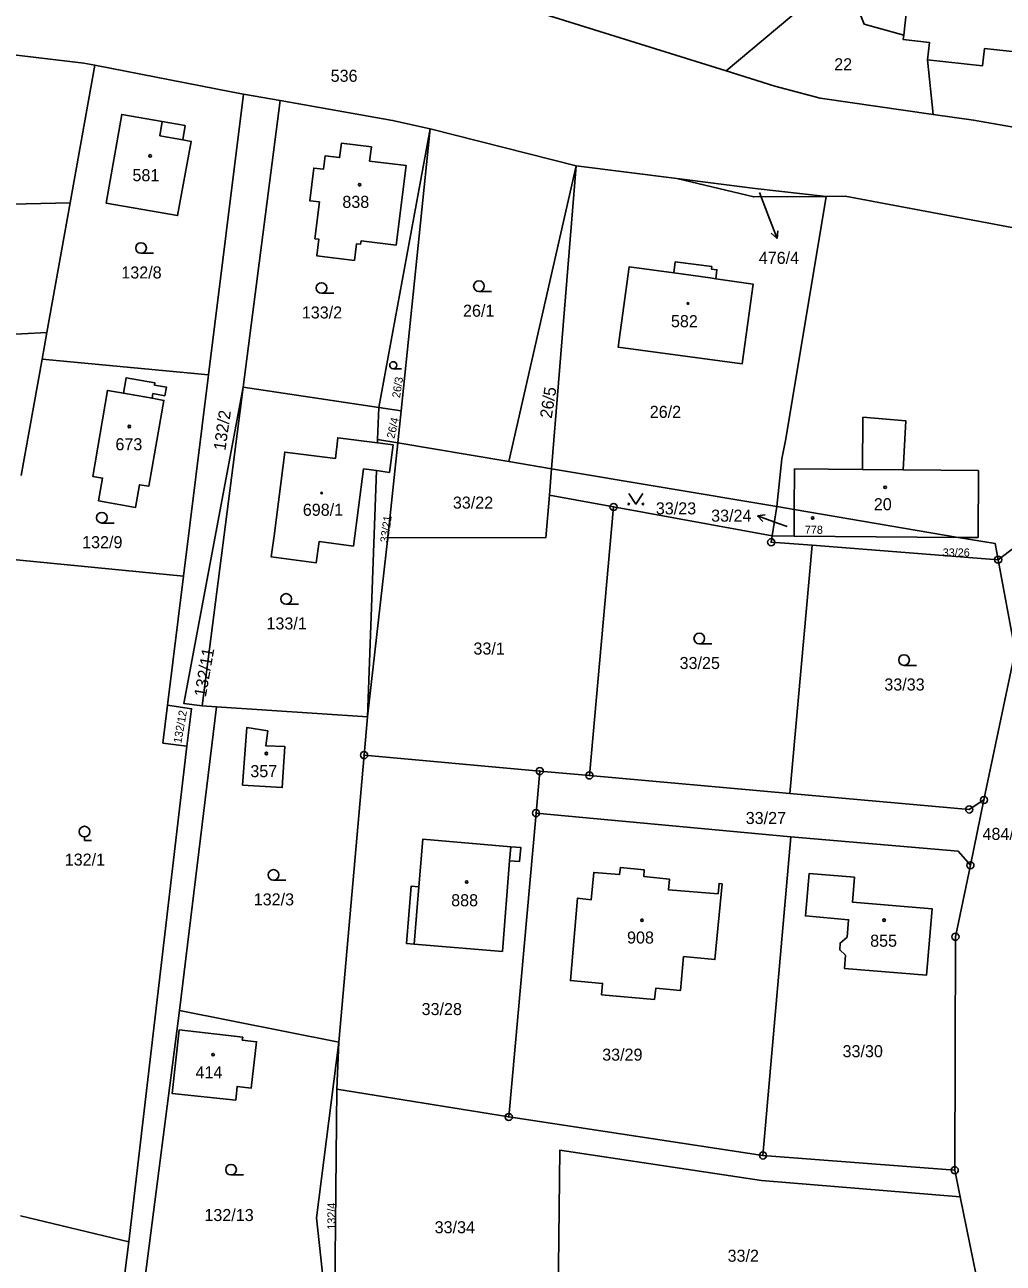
# Model space of a CAD drawing. Extents: x -725728 to -720881, y -1068679 to -1063504.
# Drawn here: x -724769.7 to -724631.7, y -1067201.5 to -1067026.9 of the extents above; entities that cross this region are included whole.
import ezdxf

# ---------------------------------------------------------------- set-up
doc = ezdxf.new("R2010")
doc.units = 0
for name, color, linetype in [('Hranice parcel', 7, 'Continuous'), ('Parcelní čísla', 7, 'Continuous'), ('Pop  PČ popisy', 7, 'Continuous'), ('Vnitřní kresba', 7, 'Continuous'), ('Značky bodu BP', 7, 'Continuous'), ('Značky budov', 7, 'Continuous'), ('Značky kultur', 7, 'Continuous')]:
    doc.layers.add(name, color=color, linetype=linetype)

# ---------------------------------------------------------------- blocks, each defined once
blk = doc.blocks.new('4.02_5')
at = {"layer": 'Značky budov'}
blk.add_circle((0, 0), 0.0117, dxfattribs=at)
blk = doc.blocks.new('4.02_4')
at = {"layer": 'Značky budov'}
blk.add_circle((-0.001, 0), 0.0175, dxfattribs=at)
blk = doc.blocks.new('4.02_3')
at = {"layer": 'Značky budov'}
blk.add_circle((-0.001, 0), 0.0175, dxfattribs=at)
blk = doc.blocks.new('1029_92')
at = {"layer": 'Pop  PČ popisy'}
for p, q in [((0, 0), (0.107, -0.28)), ((0.107, -0.28), (0.118, -0.169)), ((0.107, -0.28), (0.025, -0.205))]:
    blk.add_line(p, q, dxfattribs=at)
blk = doc.blocks.new('1029_94')
at = {"layer": 'Pop  PČ popisy'}
for p, q in [((-0.282, 0.102), (-0.171, 0.115)), ((0, 0), (-0.282, 0.102)), ((-0.282, 0.102), (-0.205, 0.021))]:
    blk.add_line(p, q, dxfattribs=at)
blk = doc.blocks.new('3.04_2')
at = {"layer": 'Značky kultur'}
blk.add_line((0.001, 0), (0.176, 0), dxfattribs=at)
blk.add_circle((0.001, 0.075), 0.075, dxfattribs=at)
blk = doc.blocks.new('3.04_5')
at = {"layer": 'Značky kultur'}
blk.add_line((0, 0), (0.118, 0), dxfattribs=at)
blk.add_circle((0, 0.05), 0.0502, dxfattribs=at)
blk = doc.blocks.new('3.14_1')
at = {"layer": 'Značky kultur'}
blk.add_lwpolyline([(-0.1, 0.15), (0, 0), (0.1, 0.15)], dxfattribs=at)
for centre in [(-0.1, 0), (0.1, 0)]:
    blk.add_circle(centre, 0.01, dxfattribs=at)
blk = doc.blocks.new('3.05_2')
at = {"layer": 'Značky kultur'}
for p, q in [((0, 0.05), (0, 0)), ((0, 0), (0.1, 0))]:
    blk.add_line(p, q, dxfattribs=at)
blk.add_circle((0, 0.125), 0.075, dxfattribs=at)
blk = doc.blocks.new('3.04_3')
at = {"layer": 'Značky kultur'}
blk.add_line((0.001, 0), (0.176, 0), dxfattribs=at)
blk.add_circle((0.001, 0.075), 0.075, dxfattribs=at)
blk = doc.blocks.new('1.05_2')
at = {"layer": 'Značky bodu BP'}
for radius in [0.05, 0.00303]:
    blk.add_circle((0, 0), radius, dxfattribs=at)
blk = doc.blocks.new('1.05_1')
at = {"layer": 'Značky bodu BP'}
for radius in [0.05, 0.00303]:
    blk.add_circle((0, 0), radius, dxfattribs=at)

msp = doc.modelspace()

# ---------------------------------------------------------------- linework, layer by layer
at = {"layer": 'Hranice parcel'}
for p, q in [((-724654.25, -1067019.5), (-724670.79, -1067033.37)), ((-724759.85, -1067032.59), (-724763.32, -1067051.97)), ((-724641.56, -1067039.51), (-724642.37, -1067031.81)), ((-724738.88, -1067036.65), (-724743.79, -1067076.25)), ((-724738.92, -1067077.99), (-724733.71, -1067037.56)), ((-724733.71, -1067037.56), (-724738.88, -1067036.65)), ((-724712.52, -1067041.56), (-724719.79, -1067080.85)), ((-724712.52, -1067041.56), (-724716.63, -1067081.32)), ((-724691.94, -1067046.77), (-724712.52, -1067041.56)), ((-724701.43, -1067088.49), (-724691.94, -1067046.77)), ((-724691.94, -1067046.77), (-724695.41, -1067089.5)), ((-724677.75, -1067048.56), (-724691.94, -1067046.77)), ((-724795.59, -1067052.75), (-724763.32, -1067051.97)), ((-724763.32, -1067051.97), (-724766.6, -1067070.28)), ((-724786.39, -1067071.29), (-724766.6, -1067070.28)), ((-724766.6, -1067070.28), (-724767.27, -1067074.02)), ((-724767.27, -1067074.02), (-724770.22, -1067090.46)), ((-724767.27, -1067074.02), (-724743.79, -1067076.25)), ((-724743.79, -1067076.25), (-724747.31, -1067104.65)), ((-724738.92, -1067077.99), (-724744.71, -1067122.95)), ((-724719.79, -1067080.85), (-724738.92, -1067077.99)), ((-724719.79, -1067080.85), (-724719.95, -1067085.37)), ((-724719.79, -1067080.85), (-724716.63, -1067081.32)), ((-724716.63, -1067081.32), (-724717.11, -1067085.85)), ((-724719.95, -1067085.37), (-724719.97, -1067085.85)), ((-724719.95, -1067085.37), (-724717.11, -1067085.85)), ((-724718.52, -1067099.21), (-724717.11, -1067085.85)), ((-724717.11, -1067085.85), (-724701.43, -1067088.49)), ((-724701.43, -1067088.49), (-724695.41, -1067089.5)), ((-724720.11, -1067089.76), (-724721.37, -1067124.47)), ((-724695.71, -1067093.21), (-724695.41, -1067089.5)), ((-724695.41, -1067089.5), (-724663.61, -1067094.84)), ((-724686.67, -1067094.88), (-724695.71, -1067093.21)), ((-724690.07, -1067132.75), (-724686.67, -1067094.88)), ((-724686.67, -1067094.88), (-724664.28, -1067098.96)), ((-724664.28, -1067098.96), (-724663.61, -1067094.84)), ((-724663.61, -1067094.84), (-724661.17, -1067095.25)), ((-724661.17, -1067095.25), (-724661.19, -1067099.02)), ((-724661.17, -1067095.25), (-724638.07, -1067099.17)), ((-724664.28, -1067098.96), (-724661.19, -1067099.02)), ((-724661.19, -1067099.02), (-724638.07, -1067099.17)), ((-724718.52, -1067099.21), (-724721.37, -1067124.47)), ((-724661.81, -1067135.28), (-724658.67, -1067100.29)), ((-724658.67, -1067100.29), (-724632.41, -1067102.32)), ((-724632.41, -1067102.32), (-724628.43, -1067099.3)), ((-724747.31, -1067104.65), (-724772.33, -1067102.22)), ((-724749.57, -1067122.85), (-724747.31, -1067104.65)), ((-724750.23, -1067128.2), (-724749.57, -1067122.85)), ((-724747.87, -1067165.91), (-724742.67, -1067123.08)), ((-724742.67, -1067123.08), (-724744.71, -1067122.95)), ((-724721.37, -1067124.47), (-724742.67, -1067123.08)), ((-724721.37, -1067124.47), (-724721.85, -1067129.88)), ((-724755.04, -1067198.52), (-724746.86, -1067128.62)), ((-724746.86, -1067128.62), (-724750.23, -1067128.2)), ((-724721.85, -1067129.88), (-724725.41, -1067170.37)), ((-724721.85, -1067129.88), (-724697.07, -1067132.14)), ((-724697.6, -1067138.06), (-724697.07, -1067132.14)), ((-724697.07, -1067132.14), (-724690.07, -1067132.75)), ((-724690.07, -1067132.75), (-724661.81, -1067135.28)), ((-724634.41, -1067136.21), (-724636.32, -1067145.42)), ((-724701.44, -1067180.92), (-724697.6, -1067138.06)), ((-724661.64, -1067141.39), (-724697.6, -1067138.06)), ((-724665.59, -1067186.35), (-724661.64, -1067141.39)), ((-724752.93, -1067204.93), (-724747.87, -1067165.91)), ((-724747.87, -1067165.91), (-724725.41, -1067170.37)), ((-724725.41, -1067170.37), (-724725.72, -1067176.99)), ((-724726.02, -1067210.09), (-724725.72, -1067176.99)), ((-724725.72, -1067176.99), (-724701.44, -1067180.92)), ((-724701.44, -1067180.92), (-724665.59, -1067186.35)), ((-724638.53, -1067188.43), (-724665.59, -1067186.35)), ((-724638.53, -1067188.43), (-724637.76, -1067192.18)), ((-724633.96, -1067210.77), (-724637.76, -1067192.18)), ((-724770.31, -1067194.87), (-724755.04, -1067198.52)), ((-724755.04, -1067198.52), (-724760.01, -1067236.9))]:
    msp.add_line(p, q, dxfattribs=at)
for points in [[(-724719.5, -1067017.82), (-724705.96, -1067022.33), (-724704.31, -1067022.88), (-724670.79, -1067033.37)], [(-724644.48, -1067016.97), (-724645.72, -1067028.33)], [(-724645.72, -1067028.33), (-724651.32, -1067026.79), (-724654.25, -1067019.5)], [(-724642.37, -1067031.81), (-724634.6, -1067032.65), (-724634.33, -1067030.21), (-724627.36, -1067030.96), (-724627.63, -1067033.45), (-724619.76, -1067034.3), (-724619.49, -1067031.81), (-724612.52, -1067032.56), (-724612.78, -1067035.05), (-724604.91, -1067035.9), (-724604.65, -1067033.41), (-724600.76, -1067033.83), (-724599.91, -1067025.93)], [(-724645.72, -1067028.33), (-724645.79, -1067028.97), (-724642.1, -1067029.37), (-724642.37, -1067031.81)], [(-724759.85, -1067032.59), (-724761.39, -1067032.29), (-724778.81, -1067030.24), (-724796.36, -1067029.37), (-724825.19, -1067030.97), (-724834.64, -1067033.08)], [(-724738.88, -1067036.65), (-724740.6, -1067036.35), (-724759.85, -1067032.59)], [(-724670.79, -1067033.37), (-724663.92, -1067035.52), (-724657.53, -1067037.25), (-724641.56, -1067039.51)], [(-724712.52, -1067041.56), (-724717.83, -1067040.37), (-724733.71, -1067037.56)], [(-724747.07, -1067041.09), (-724750.32, -1067040.52), (-724756.03, -1067039.52), (-724758.22, -1067052.03), (-724748.17, -1067053.79), (-724746.24, -1067043.32), (-724747.42, -1067043.11), (-724747.07, -1067041.09)], [(-724641.56, -1067039.51), (-724635.9, -1067040.31), (-724605.27, -1067045.69), (-724604.4, -1067049.16)], [(-724723.19, -1067060.11), (-724728.5, -1067059.47), (-724728.22, -1067057.12), (-724728.78, -1067057.05), (-724728.15, -1067051.87), (-724729.53, -1067051.7), (-724728.95, -1067047.09), (-724727.59, -1067047.25), (-724727.33, -1067045.36), (-724725.3, -1067045.6), (-724725.04, -1067043.57), (-724720.81, -1067044.11), (-724721.09, -1067046.09), (-724715.93, -1067046.72), (-724717.35, -1067057.95), (-724722.28, -1067057.36), (-724722.35, -1067057.81), (-724722.92, -1067057.75), (-724723.19, -1067060.11)], [(-724656.65, -1067051.08), (-724666.88, -1067051.16), (-724677.75, -1067048.56)], [(-724656.65, -1067051.08), (-724666.68, -1067049.96), (-724677.75, -1067048.56)], [(-724656.65, -1067051.08), (-724662.37, -1067085.26), (-724662.92, -1067088.09), (-724663.61, -1067094.84)], [(-724629.22, -1067055.72), (-724653.99, -1067051.06), (-724656.65, -1067051.08)], [(-724672.82, -1067060.98), (-724672.87, -1067061.33), (-724672.08, -1067061.43), (-724672.25, -1067062.69), (-724666.98, -1067063.45), (-724668.54, -1067074.7), (-724686, -1067072.35), (-724684.47, -1067061.02), (-724678.18, -1067061.88), (-724677.96, -1067060.33), (-724672.82, -1067060.98)], [(-724749.97, -1067079.2), (-724751.64, -1067078.9), (-724751.76, -1067079.56), (-724750.09, -1067079.86), (-724752.24, -1067091.97), (-724753.52, -1067091.74), (-724754.09, -1067094.94), (-724759.31, -1067094.01), (-724758.74, -1067090.81), (-724760.12, -1067090.57), (-724758.06, -1067078.44), (-724755.8, -1067078.84), (-724755.41, -1067076.67), (-724751.37, -1067077.39), (-724751.43, -1067077.69), (-724749.75, -1067077.98), (-724749.97, -1067079.2)], [(-724744.71, -1067122.95), (-724747.29, -1067122.59), (-724738.92, -1067077.99)], [(-724719.97, -1067085.85), (-724725.58, -1067085.12), (-724725.9, -1067088.07), (-724733.04, -1067087.15), (-724734.56, -1067098.95), (-724734.94, -1067101.92), (-724728.6, -1067102.74), (-724728.21, -1067099.77), (-724723.36, -1067100.41), (-724721.93, -1067089.52), (-724720.11, -1067089.76)], [(-724720.11, -1067089.76), (-724718.27, -1067090), (-724717.76, -1067086.14), (-724719.97, -1067085.85)], [(-724695.71, -1067093.21), (-724696.22, -1067099.25), (-724718.52, -1067099.21)], [(-724658.67, -1067100.29), (-724664.43, -1067099.85), (-724664.28, -1067098.96)], [(-724638.07, -1067099.17), (-724632.83, -1067100.06), (-724632.41, -1067102.32)], [(-724632.41, -1067102.32), (-724630.03, -1067115.24), (-724634.41, -1067136.21)], [(-724749.57, -1067122.85), (-724746.18, -1067123.34), (-724746.86, -1067128.62)], [(-724735.42, -1067126.44), (-724735.73, -1067128.56), (-724733.03, -1067128.69), (-724733.4, -1067134.47), (-724738.99, -1067134.11), (-724738.41, -1067126), (-724735.42, -1067126.44)], [(-724661.81, -1067135.28), (-724636.49, -1067137.55), (-724634.41, -1067136.21)], [(-724714.13, -1067148.47), (-724713.57, -1067141.76), (-724701.16, -1067142.81), (-724699.76, -1067142.91), (-724699.93, -1067144.87), (-724701.32, -1067144.79), (-724702.34, -1067157.57), (-724714.79, -1067156.56), (-724715.89, -1067156.43), (-724715.23, -1067148.38), (-724714.13, -1067148.47)], [(-724661.64, -1067141.39), (-724638.03, -1067143.44), (-724636.32, -1067145.42)], [(-724671.93, -1067149.45), (-724671.77, -1067147.97), (-724671.36, -1067148.04), (-724672.37, -1067158.71), (-724676.78, -1067158.29), (-724677.22, -1067163.07), (-724680.69, -1067162.74), (-724680.87, -1067164.34), (-724688.35, -1067163.68), (-724688.22, -1067162.08), (-724692.76, -1067161.68), (-724691.76, -1067150.07), (-724689.84, -1067150.3), (-724689.45, -1067146.42), (-724685.81, -1067146.7), (-724685.7, -1067145.71), (-724682.34, -1067146.07), (-724682.4, -1067146.99), (-724678.76, -1067147.38), (-724678.91, -1067148.9), (-724671.93, -1067149.45)], [(-724636.32, -1067145.42), (-724638.43, -1067155.5), (-724638.53, -1067188.43)], [(-724653.95, -1067158.08), (-724654.76, -1067157.36), (-724654.7, -1067156.39), (-724653.71, -1067155.55), (-724653.52, -1067153.11), (-724659.6, -1067152.57), (-724659.07, -1067146.56), (-724652.68, -1067147.12), (-724652.98, -1067150.6), (-724641.72, -1067151.57), (-724642.52, -1067160.94), (-724654.1, -1067159.96), (-724653.95, -1067158.08)], [(-724739.95, -1067178.57), (-724739.77, -1067176.61), (-724737.76, -1067176.84), (-724737.01, -1067170.3), (-724739.03, -1067170.07), (-724738.98, -1067169.67), (-724747.93, -1067168.65), (-724748.95, -1067177.6), (-724739.95, -1067178.57)], [(-724725.41, -1067170.37), (-724728.55, -1067195.16), (-724726.95, -1067209.91)], [(-724637.76, -1067192.18), (-724665.81, -1067189.86), (-724694.22, -1067185.59), (-724694.52, -1067210.34)]]:
    msp.add_lwpolyline(points, dxfattribs=at)
at = {"layer": 'Pop  PČ popisy'}
for p, q in [((-724666.07, -1067050.55), (-724664.67, -1067054.24)), ((-724662.17, -1067097.66), (-724663.55, -1067097.15))]:
    msp.add_line(p, q, dxfattribs=at)
at = {"layer": 'Vnitřní kresba'}
for p, q in [((-724750.32, -1067040.52), (-724750.67, -1067042.54)), ((-724750.67, -1067042.54), (-724747.42, -1067043.11)), ((-724678.18, -1067061.88), (-724673.04, -1067062.59)), ((-724673.04, -1067062.59), (-724672.25, -1067062.69)), ((-724755.8, -1067078.84), (-724751.76, -1067079.56)), ((-724651.55, -1067089.59), (-724651.48, -1067082.24)), ((-724651.48, -1067082.24), (-724645.42, -1067082.73)), ((-724645.79, -1067089.64), (-724645.42, -1067082.73)), ((-724661.14, -1067089.5), (-724661.17, -1067095.25)), ((-724651.55, -1067089.59), (-724661.14, -1067089.5)), ((-724645.79, -1067089.64), (-724651.55, -1067089.59)), ((-724635.19, -1067089.74), (-724645.79, -1067089.64)), ((-724635.22, -1067099.19), (-724635.19, -1067089.74)), ((-724635.22, -1067099.19), (-724638.07, -1067099.17)), ((-724701.32, -1067144.79), (-724701.16, -1067142.81)), ((-724714.13, -1067148.47), (-724714.79, -1067156.56))]:
    msp.add_line(p, q, dxfattribs=at)

# ---------------------------------------------------------------- block references
at = {"layer": 'Pop  PČ popisy', "xscale": 10, "yscale": 10}
for name, p in [('1029_92', (-724664.67, -1067054.24)), ('1029_94', (-724663.55, -1067097.15))]:
    msp.add_blockref(name, p, dxfattribs=at)
at = {"layer": 'Značky bodu BP', "xscale": 10, "yscale": 10}
for name, p in [('1.05_2', (-724686.67, -1067094.88)), ('1.05_1', (-724664.43, -1067099.85)), ('1.05_1', (-724632.41, -1067102.32)), ('1.05_2', (-724721.85, -1067129.88)), ('1.05_2', (-724697.07, -1067132.14)), ('1.05_1', (-724690.07, -1067132.75)), ('1.05_1', (-724636.49, -1067137.55)), ('1.05_1', (-724634.41, -1067136.21)), ('1.05_1', (-724697.6, -1067138.06)), ('1.05_2', (-724636.32, -1067145.42)), ('1.05_1', (-724638.43, -1067155.5)), ('1.05_2', (-724701.44, -1067180.92)), ('1.05_1', (-724665.59, -1067186.35)), ('1.05_2', (-724638.53, -1067188.43))]:
    msp.add_blockref(name, p, dxfattribs=at)
at = {"layer": 'Značky budov', "xscale": 10, "yscale": 10}
for name, p in [('4.02_3', (-724752.02, -1067045.37)), ('4.02_3', (-724722.48, -1067049.44)), ('4.02_5', (-724676.16, -1067066.18)), ('4.02_3', (-724754.96, -1067083.54)), ('4.02_3', (-724648.34, -1067092.11)), ('4.02_5', (-724727.83, -1067092.91)), ('4.02_4', (-724658.57, -1067096.43)), ('4.02_4', (-724735.63, -1067129.66)), ('4.02_3', (-724707.37, -1067147.77)), ('4.02_4', (-724682.65, -1067153.17)), ('4.02_4', (-724648.49, -1067153.16)), ('4.02_3', (-724743.14, -1067172.12))]:
    msp.add_blockref(name, p, dxfattribs=at)
at = {"layer": 'Značky kultur', "xscale": 10, "yscale": 10}
for name, p in [('3.04_2', (-724753.33, -1067059.11)), ('3.04_2', (-724727.87, -1067064.75)), ('3.04_2', (-724705.66, -1067064.5)), ('3.04_5', (-724717.74, -1067075.4)), ('3.14_1', (-724683.52, -1067094.47)), ('3.04_3', (-724758.86, -1067097.15)), ('3.04_2', (-724732.85, -1067108.61)), ('3.04_2', (-724674.58, -1067114.19)), ('3.04_2', (-724645.7, -1067117.22)), ('3.05_2', (-724761.3, -1067141.92)), ('3.04_2', (-724734.65, -1067147.53)), ('3.04_2', (-724740.63, -1067189.1))]:
    msp.add_blockref(name, p, dxfattribs=at)

# ---------------------------------------------------------------- texts
at = {"layer": 'Parcelní čísla'}
for s, height, p in [('22', 1.7, (-724655.54, -1067033.3)), ('536', 1.7, (-724726.57, -1067034.92)), ('581', 1.7, (-724754.53, -1067048.94)), ('838', 1.7, (-724724.92, -1067052.7)), ('476/4', 1.7, (-724666.18, -1067060.6)), ('132/8', 1.7, (-724756.1, -1067062.66)), ('133/2', 1.7, (-724730.64, -1067068.3)), ('26/1', 1.7, (-724707.9, -1067068.05)), ('582', 1.7, (-724678.57, -1067069.53)), ('26/2', 1.7, (-724681.56, -1067082.32)), ('673', 1.7, (-724756.93, -1067086.89)), ('33/22', 1.7, (-724709.33, -1067095.12)), ('20', 1.7, (-724649.95, -1067095.35)), ('698/1', 1.7, (-724730.5, -1067096.13)), ('33/23', 1.7, (-724680.7, -1067095.93)), ('33/24', 1.7, (-724672.9, -1067096.96)), ('132/9', 1.7, (-724761.63, -1067100.7)), ('778', 1.14, (-724659.68, -1067098.67)), ('33/26', 1.14, (-724640.23, -1067101.87)), ('133/1', 1.7, (-724735.63, -1067112.16)), ('33/1', 1.7, (-724706.43, -1067115.7)), ('33/25', 1.7, (-724677.35, -1067117.74)), ('33/33', 1.7, (-724648.47, -1067120.77)), ('357', 1.7, (-724737.9, -1067132.99)), ('33/27', 1.7, (-724668.02, -1067139.6)), ('484/3', 1.7, (-724634.62, -1067141.84)), ('132/1', 1.7, (-724764.08, -1067145.47)), ('132/3', 1.7, (-724737.42, -1067151.08)), ('888', 1.7, (-724709.57, -1067151.2)), ('908', 1.7, (-724684.76, -1067156.46)), ('855', 1.7, (-724650.47, -1067156.91)), ('33/28', 1.7, (-724713.74, -1067166.55)), ('33/29', 1.7, (-724688.27, -1067172.98)), ('33/30', 1.7, (-724654.36, -1067172.49)), ('414', 1.7, (-724745.63, -1067175.46)), ('132/13', 1.7, (-724744.38, -1067195.6)), ('33/34', 1.7, (-724711.9, -1067197.32)), ('33/2', 1.7, (-724670.58, -1067201.34))]:
    msp.add_text(s, height=height, dxfattribs=at).set_placement(p)
for s, height, rotation, p in [('26/3', 1.14, 81, (-724716.8, -1067079.57)), ('26/5', 1.7, 81, (-724695.4, -1067082.47)), ('132/2', 1.7, 82, (-724741.42, -1067087)), ('26/4', 1.14, 77, (-724717.59, -1067085.31)), ('33/21', 1.14, 82, (-724718.48, -1067099.96)), ('132/11', 1.7, 80, (-724744.18, -1067121.77)), ('132/12', 1.14, 80, (-724747.64, -1067128.27)), ('132/4', 1.14, 90, (-724725.89, -1067196.82))]:
    msp.add_text(s, height=height, rotation=rotation, dxfattribs=at).set_placement(p)

doc.saveas('drawing.dxf')
